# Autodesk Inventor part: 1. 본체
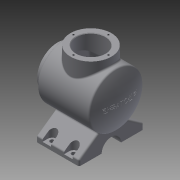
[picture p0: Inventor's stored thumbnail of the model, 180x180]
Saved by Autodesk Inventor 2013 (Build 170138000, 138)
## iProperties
Created: 2017-04
Part Number: 1. 본체
Material: 일반
Document SubType Name: Modeling
Designer: Administrator
Density: 1 g/cm^3
Author: Administrator
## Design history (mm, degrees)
sketch "스케치1"
  geometry: L1 (-54, 0)-(54, 0); L2 (-54, 0)-(-54, 50); L3 (-54, 50)-(42.336, 50); A1 r 113 centre (-59, 0) between (54, 0) and (42.336, 50); 2 further points
  constraints: 6 end point, 2 perpendicular, 2 point on circle, 1 centre point, 1 coincident, 1 horizontal, 1 midpoint, 1 point on line
  dimensions: "d0" = 108 distance of L1.start L1.end; "d4" = 100 diameter of L3 L1; "d5" = 113 radius of A1
revolve "회전1" sketch "스케치1" stored, may be unused: angle "d7" = 90 deg
sketch "스케치3"
  geometry: C1 r 50 at (0, 0) reference; C2 r 38 at (0, 0)
  constraints: 1 centre point, 1 coincident
  dimensions: "d13" = 76 diameter of C2
extrude "돌출1" join sketch "스케치3" distance "d15" = 12; taper "d16" = 0 deg
sketch "스케치2"
  geometry: L1 (66, 0)-(-54, 0); L2 (44, 0)-(44, -40); L3 (44, -40)-(-35.916, -40); L4 (54, -50)-(-42.336, -50) reference; L5 (-42.336, 50)-(54, 50) reference; L6 (54, 38)-(66, 38) reference; L7 (66, 38)-(66, -38) reference; L8 (66, -38)-(54, -38) reference; L9 (54, -38)-(54, -50) reference; L10 (54, 50)-(54, 38) reference; A1 r 113 centre (59, 0) between (-42.336, 50) and (-42.336, -50) reference; A2 r 103 centre (59, 0) between (-44, 0) and (-35.916, -40); 2 further points
  constraints: 6 end point, 3 point on circle, 3 point on line, 2 perpendicular, 1 centre point, 1 coincident, 1 horizontal, 1 midpoint
  dimensions: "d8" = 80 diameter of L3 L1; "d11" = 10 radial gap between concentric circles of A1 A2; "d17" = 22 distance between parallel lines of L7 L2
revolve "회전3" sketch "스케치2" stored, may be unused: angle "d19" = 90 deg
hole "구멍1" diameter "d22" = 54; stored, may be unused: countersink angle "d26" = 90 deg, drill point angle "d28" = 0 deg; dims "d23" = 6, "d24" = 4, "d25" = 2, "d27" = 20, "d33" = 10, "d34" = 10
node "작업 평면1"
sketch "스케치4"
  geometry: L1 (-21.584, -45.101)-(-60, -72); L2 (-60, -72)-(-60, -82); L3 (-60, -82)-(60, -82); L4 (60, -82)-(60, -72); L5 (60, -72)-(21.584, -45.101); C1 r 27 at (0, 0) reference; A1 r 50 centre (0, 0) between (21.584, -45.101) and (-21.584, -45.101) reference; 2 further points
  constraints: 10 end point, 2 perpendicular, 2 point on circle, 1 horizontal alignment, 1 midpoint, 1 vertical, 1 vertical alignment
  dimensions: "d38" = 120 distance between parallel lines of L4 L2; "d40" = 10 distance of L2.end L1.end; "d41" = 82 distance from line of L3 point (0, 0); "d42" = 55 deg angle of L4 L5; "d43" = 55 deg angle of L1 L2
extrude "돌출2" join sketch "스케치4" distance "d44" = 80; taper "d45" = 0 deg
sketch "스케치5"
  geometry: L1 (-60, -82)-(60, -82) reference; C1 r 18 at (0, -82)
  constraints: 1 centre point, 1 midpoint
  dimensions: "d46" = 18 radius of C1
extrude "돌출3" cut sketch "스케치5" stored distance "d48" = 80; taper "d49" = 0 deg
node "작업 평면2"
sketch "스케치6"
  geometry: L1 (66, -38)-(66, 38) reference; L2 (54, 50)-(54, -50) reference; C1 r 38 at (4, 0); 1 further point
  constraints: 2 coincident, 1 centre point
  dimensions: "d54" = 76 diameter of C1; "d113" = 50 distance from line of L2 point (4, 0); "d114" = 72.71864 distance of L1.end C1.centre
extrude "돌출4" join sketch "스케치6" stored distance "d56" = 80; taper "d57" = 0 deg
hole "구멍2" diameter "d60" = 54; stored, may be unused: countersink angle "d64" = 90 deg, drill point angle "d66" = 0 deg; dims "d61" = 6, "d62" = 4, "d63" = 2, "d65" = 20, "d67" = 10, "d68" = 10
sketch "스케치7" dims "d69" = 65
  geometry: C1 r 27 at (0, 0) reference; 2 further points
  constraints: 2 vertical alignment, 1 coincident, 2 other
hole "구멍3" sketch "스케치7" at (0, 32.5) diameter "d71" = 3.242; stored, may be unused: countersink angle "d75" = 90 deg, drill point angle "d77" = 118 deg; dims "d72" = 8, "d73" = 4, "d74" = 2, "d76" = 10
sketch "스케치8" dims "d81" = 65
  geometry: C1 r 27 at (0, 0) reference; 2 further points
  constraints: 2 horizontal alignment, 1 coincident, 2 other
hole "구멍4" sketch "스케치8" at (32.5, 0) diameter "d83" = 3.242; stored, may be unused: countersink angle "d87" = 90 deg, drill point angle "d89" = 118 deg; dims "d84" = 8, "d85" = 4, "d86" = 2, "d88" = 10
node "작업 평면3"
sketch "스케치9"
  geometry: L1 (80, -43.029)-(0, -43.029) reference; L2 (0, -43.029)-(0, 0) reference; L3 (0, 0)-(80, 0) reference; L4 (80, 0)-(80, -43.029) reference; L5 (0, -76.971)-(80, -76.971) reference; L6 (80, -76.971)-(80, -120) reference; L7 (80, -120)-(0, -120) reference; L8 (0, -120)-(0, -76.971) reference; L9 (28, -10)-(28, 0); L10 (12, -10)-(12, 0); A1 r 8 centre (20, -10) between (28, -10) and (12, -10); 1 further point
  constraints: 4 end point, 2 perpendicular, 2 point on circle, 2 point on line, 2 tangent, 1 centre point
  dimensions: "d94" = 16 diameter of A1; "d96" = 20 distance from line of A1.centre L2; "d97" = 10 distance from line of L3 A1.centre
extrude "돌출5" cut sketch "스케치9" stored distance "d98" = 80; taper "d99" = 0 deg
hole "구멍5" diameter "d102" = 8; stored, may be unused: countersink angle "d106" = 90 deg, drill point angle "d108" = 0 deg; dims "d100" = 10, "d101" = 10, "d103" = 8, "d104" = 4, "d105" = 2, "d107" = 10
fillet "모깎기1" dims "d115" = 3
fillet "모깎기2" dims "d116" = 3
fillet "모깎기3" dims "d117" = 3
fillet "모깎기4" dims "d118" = 3
chamfer "모따기1" distance "d119" = 1; stored, may be unused: second distance "d120" = 2, angle "d121" = 45 deg
node "작업 평면5"
sketch "스케치11"
  geometry: 2 further points
  constraints: 1 coincident, 1 other
feature "엠보싱1" sketch "스케치11" dims "d123" = 0.5, "d124" = 0
node "솔리드1"
pattern_circular "원형 패턴1" dims angle "d79" = 360 deg
pattern_circular "원형 패턴2" dims angle "d91" = 360 deg
pattern_linear "직사각형 패턴1"
mirror "대칭1"
node "절단 모서리 투영1"
node "절단 모서리 투영2"
node "절단 모서리 투영3"
other parameters: "d29" = 0.5, "d30" = 2, "d31" = 0, "d35" = -8, "d50" = 65, "d93" = -6, "d122" = 54.5
